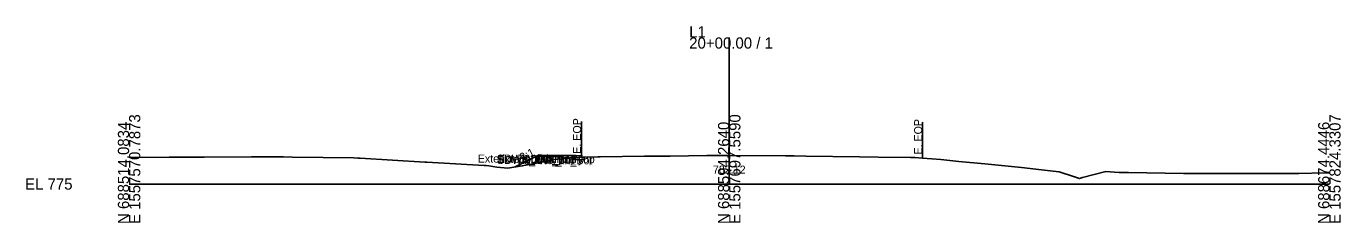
# Model space of a CAD drawing. Extents: x -26 to 2603, y -3010 to 9589.
# Drawn here: x -25.7 to 302.8, y 3490.3 to 3539.5 of the extents above; entities that cross this region are included whole.
import ezdxf

# ---------------------------------------------------------------- set-up
doc = ezdxf.new("R2010")
doc.units = 0
for name, color, linetype in [('Default', 7, 'Continuous'), ('Exist Cross Section Cell', 7, 'Continuous'), ('Exist XS Center Line Elevation Label', 7, 'Continuous'), ('Exist XS Ground Line', 7, 'Continuous'), ('Prop CMT Conc Surface', 7, 'Continuous'), ('Prop CMT Concrete Structures', 7, 'Continuous'), ('Prop CMT Slope Grass', 7, 'Continuous'), ('Prop XS Earthwork Shape', 7, 'Continuous'), ('Prop XS Label Text', 7, 'Continuous'), ('Prop XS Side Slope Text', 7, 'Continuous')]:
    doc.layers.add(name, color=color, linetype=linetype)

msp = doc.modelspace()

# ---------------------------------------------------------------- linework, layer by layer
at = {"layer": 'Exist Cross Section Cell'}
for p, q in [((150, 3500), (150, 3536.72)), ((0, 3500), (150, 3500)), ((150, 3500), (300, 3500))]:
    msp.add_line(p, q, dxfattribs=at)
at = {"layer": 'Exist XS Ground Line'}
msp.add_lwpolyline([(0, 3506.66), (10.05, 3506.75), (13.42, 3506.73), (18.74, 3506.73), (30.59, 3506.78), (38.57, 3506.82), (40.82, 3506.75), (56.15, 3506.53), (57.21, 3506.51), (57.72, 3506.49), (73.89, 3505.48), (74.4, 3505.45), (88.73, 3504.67), (89.26, 3504.64), (89.91, 3504.56), (91.92, 3504.27), (93.72, 3504.1), (94.64, 3504), (98.28, 3504.56), (103.65, 3505.57), (106.34, 3506.13), (110.89, 3506.53), (112.95, 3506.7), (117.15, 3506.84), (117.76, 3506.85), (128.8, 3506.98), (130.28, 3506.99), (135.2, 3507.01), (144.41, 3507.13), (150, 3507.12), (164.06, 3507.08), (166.22, 3507.06), (169.18, 3507.02), (182.55, 3506.79), (187.2, 3506.76), (195.29, 3506.66), (195.96, 3506.66), (196.36, 3506.62), (198.31, 3506.46), (200.67, 3506.34), (202.91, 3506.14), (207.36, 3505.65), (213.86, 3505.08), (223.03, 3504.13), (228.06, 3503.59), (230.96, 3503.26), (232.46, 3503.08), (236.3, 3501.77), (237.51, 3501.39), (238.31, 3501.61), (244.14, 3503.13), (246.26, 3503), (247.43, 3502.93), (249.77, 3502.91), (263.56, 3502.65), (270.9, 3502.64), (274.36, 3502.61), (283.13, 3502.65), (286.81, 3502.62), (292.37, 3502.66), (298.77, 3502.79), (300, 3502.81)], dxfattribs=at)
at = {"layer": 'Prop CMT Conc Surface'}
msp.add_lwpolyline([(108, 3507.17), (103, 3507.27)], dxfattribs=at)
at = {"layer": 'Prop CMT Concrete Structures'}
for points in [[(103, 3506.94), (103, 3507.27)], [(103, 3507.27), (108, 3507.17)], [(108, 3506.84), (103, 3506.94)], [(108, 3507.17), (108, 3506.84)], [(111.25, 3507.11), (111.25, 3506.09), (113.75, 3506.14)], [(111.75, 3506.61), (111.75, 3507.11), (111.25, 3507.11)], [(113.75, 3506.73), (111.75, 3506.61)], [(113.75, 3506.14), (113.75, 3506.73)]]:
    msp.add_lwpolyline(points, dxfattribs=at)
at = {"layer": 'Prop CMT Slope Grass'}
for p, q in [((102.5, 3507.28), (96.52, 3504.29)), ((103, 3507.27), (102.5, 3507.28)), ((111.25, 3507.11), (108, 3507.17)), ((111.25, 3507.11), (111.25, 3506.54))]:
    msp.add_line(p, q, dxfattribs=at)
at = {"layer": 'Prop XS Earthwork Shape'}
for points in [[(111.25, 3507.11), (108, 3507.17), (108, 3506.84), (103, 3506.94), (103, 3507.27), (102.5, 3507.28), (96.52, 3504.29), (98.28, 3504.56), (103.65, 3505.57), (106.34, 3506.13), (110.89, 3506.53), (111.25, 3506.56)], [(111.25, 3506.56), (111.75, 3506.61), (113.75, 3506.73), (113.75, 3506.14), (111.25, 3506.09), (111.25, 3506.54)], [(112.95, 3506.7), (113.75, 3506.73), (111.75, 3506.61)]]:
    msp.add_lwpolyline(points, close=True, dxfattribs=at)
at = {"layer": 'Prop XS Label Text'}
for p, q in [((113.06, 3515.66), (113.06, 3506.66)), ((198.31, 3515.46), (198.31, 3506.46))]:
    msp.add_line(p, q, dxfattribs=at)

# ---------------------------------------------------------------- texts
at = {"layer": 'Default'}
for s, height, p in [('Exterior Boundary', 2, (87.14, 3505.38)), ('SDWK_Out_Top', 2, (91.93, 3505.38)), ('SDWK_Out_Bot', 2, (91.96, 3505.04)), ('Exterior Boundary', 2, (92.14, 3505.28)), ('SDWK_In_Top', 2, (98.55, 3505.28)), ('SDWK_In_Bot', 2, (98.58, 3504.94)), ('-', 0.0001, (0, 3500))]:
    msp.add_text(s, height=height, dxfattribs=at).set_placement(p)
at = {"layer": 'Exist Cross Section Cell'}
for s, p in [('L1', (140, 3536.72)), ('20+00.00 / 1', (140, 3533.92)), ('EL 775', (-26, 3498.6))]:
    msp.add_text(s, height=2.8, dxfattribs=at).set_placement(p)
for s, p in [('N 688514.0834', (0, 3490)), ('E 1557570.7873', (2.8, 3490)), ('N 688594.2640', (150, 3490)), ('E 1557697.5590', (152.8, 3490)), ('N 688674.4446', (300, 3490)), ('E 1557824.3307', (302.8, 3490))]:
    msp.add_text(s, height=2.8, rotation=90, dxfattribs=at).set_placement(p)
at = {"layer": 'Exist XS Center Line Elevation Label'}
msp.add_text('782.12', height=2, dxfattribs=at).set_placement((145.92, 3502.62))
at = {"layer": 'Prop XS Label Text'}
for p in [(112.96, 3507.58), (198.21, 3507.38)]:
    msp.add_text('E. EOP', height=2, rotation=90, dxfattribs=at).set_placement(p)
at = {"layer": 'Prop XS Side Slope Text'}
msp.add_text('2:1', height=2, rotation=26.5651, dxfattribs=at).set_placement((98.22, 3505.64))

doc.saveas('drawing.dxf')
